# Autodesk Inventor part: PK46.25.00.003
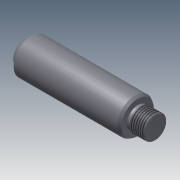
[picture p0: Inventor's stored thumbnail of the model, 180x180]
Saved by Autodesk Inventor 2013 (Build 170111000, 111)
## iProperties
Created: 2005-05
Part Number: PK46.25.00.003
Material: Steel, Mild
Document SubType Name: Modeling
Designer: PVitaliy
Manufacturer: Standard
Standards Organization: Custom
Density: 7.86 g/cm^3
Author: PVitaliy
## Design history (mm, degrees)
sketch "Эскиз2"
  geometry: L1 (0, 0)-(95.139, 0); L2 (0, 0)-(0, 25.897); L3 (0, 25.897)-(13, 35); L4 (13, 35)-(15, 35); L5 (15, 35)-(15, 40); L6 (15, 40)-(249, 40); L7 (249, 40)-(255, 36.536); L8 (255, 36.536)-(255, 24.5); L9 (255, 24.5)-(261, 24.5); L10 (261, 24.5)-(262.5, 26); L11 (262.5, 26)-(295, 26); L12 (295, 26)-(295, 0); L13 (295, 0)-(0, 0)
  constraints: 26 end point, 6 horizontal, 4 vertical, 1 other
  dimensions: "d0" = 70 diameter of L4 L1; "d1" = 35 deg angle of L3 L4; "d2" = 15 distance between parallel lines of L5 L2; "d3" = 2 distance of L3.end L4.end; "d4" = 80 diameter of L6 L1; "d5" = 240 distance between parallel lines of L8 L5; "d6" = 30 deg angle of L6 L7; "d7" = 6 horizontal distance of L6.end L7.end; "d8" = 295 distance between parallel lines of L12 L2; "d9" = 52 diameter of L11 L1; "d10" = 6 distance of L8.end L9.end; "d11" = 49 diameter of L9 L1; "d12" = 45 deg angle of L10 L9
revolve "Вращение1" sketch "Эскиз2" stored, may be unused: angle "d13" = 90 deg
feature "Резьба1" dims "d14" = 10, "d15" = 0
chamfer "Фаска1" distance "d16" = 1.6; stored, may be unused: second distance "d17" = 2, angle "d18" = 45 deg
fillet "Сопряжение1" dims "d19" = 1, "d20" = 0.5
body "Solid1"
